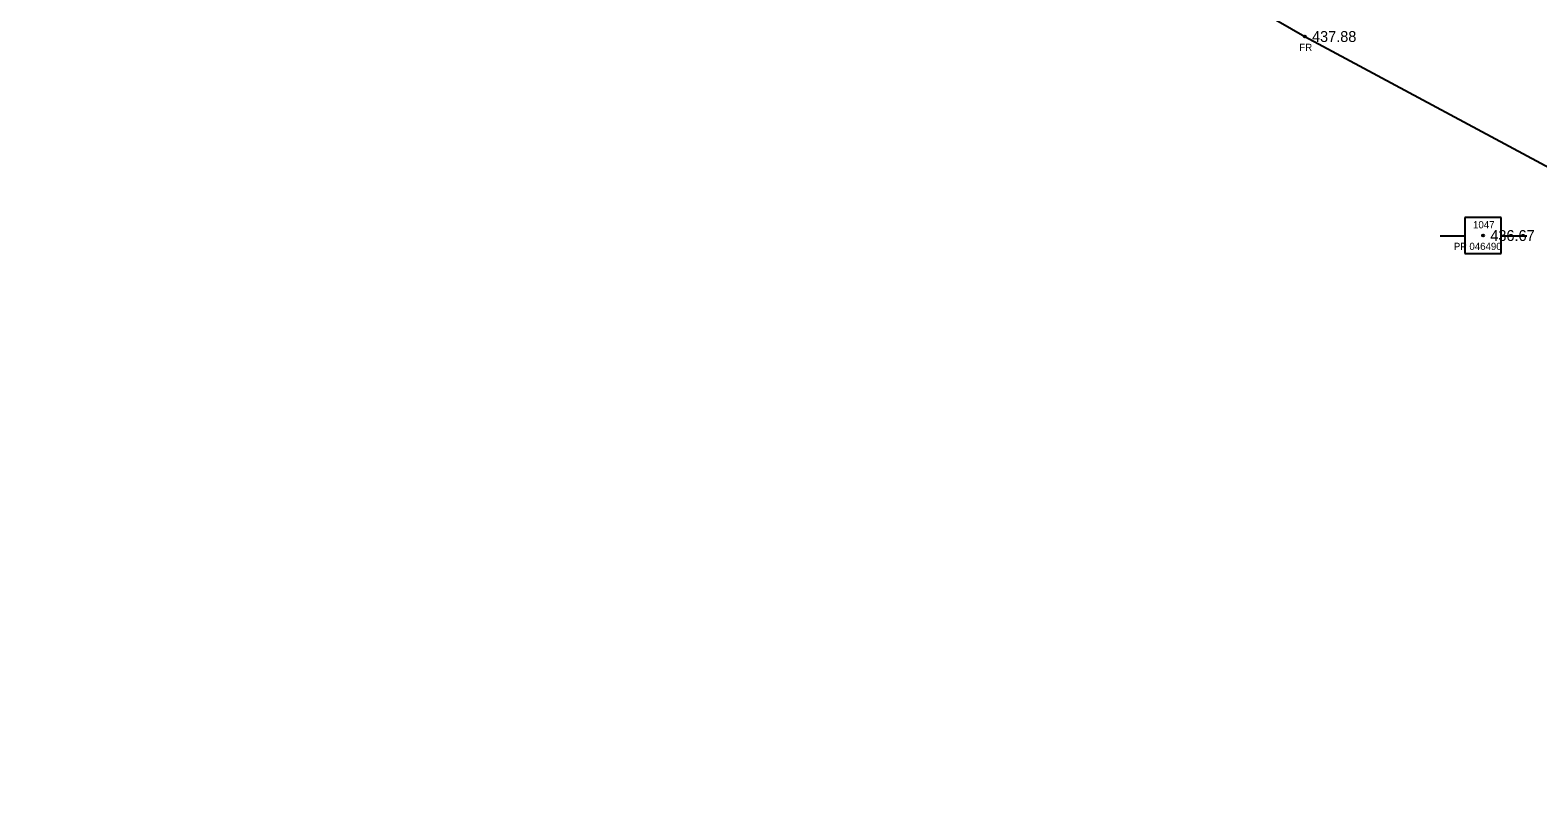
# Model space of a CAD drawing. Extents: x 1611865 to 1617004, y 775289 to 778546.
# Drawn here: x 1613852.1 to 1614060.8, y 777874.5 to 777980.8 of the extents above; entities that cross this region are included whole.
import ezdxf

# ---------------------------------------------------------------- set-up
doc = ezdxf.new("R2010")
doc.units = 0
for name, color, linetype in [('Default', 7, 'Continuous'), ('RD_EX_Fence_Other', 7, 'Continuous'), ('RD_EX_Fence_Other_txCode', 7, 'Continuous'), ('RD_EX_TX_Fence_Other_ELEV', 7, 'Continuous'), ('RD_EX_UT', 7, 'Continuous'), ('RD_EX_UT_txCode', 7, 'Continuous'), ('RD_HC_Cl', 7, 'Continuous'), ('RD_HC_Survey_ELEV', 7, 'Continuous'), ('RD_SMD_Locator', 7, 'Continuous')]:
    doc.layers.add(name, color=color, linetype=linetype)

msp = doc.modelspace()

# ---------------------------------------------------------------- linework, layer by layer
at = {"layer": 'Default'}
msp.add_arc((1613334.62, 776765.46), 1432.38, 51.01411, 67.14296, dxfattribs=at)
msp.add_arc((1613334.62, 776765.46), 1432.38, 51.01411, 67.14296, dxfattribs=at)
at = {"layer": 'RD_EX_Fence_Other'}
msp.add_lwpolyline([(1613852.08, 778066.01), (1613898.03, 778046.63), (1613942.24, 778026.73), (1613986.54, 778004.12), (1614028.52, 777979.95), (1614066.85, 777959.39), (1614112.82, 777929.4), (1614150.64, 777902.78), (1614189.71, 777873.35), (1614229.91, 777841.27), (1614268.42, 777810.69), (1614347.33, 777746.8), (1614401.12, 777703.98), (1614396.2, 777691.06)], dxfattribs=at)
at = {"layer": 'RD_EX_UT'}
for p, q in [((1614055.69, 777954.92), (1614050.69, 777954.92)), ((1614050.69, 777954.92), (1614050.69, 777949.92)), ((1614055.69, 777949.92), (1614055.69, 777954.92)), ((1614047.25, 777952.35), (1614050.72, 777952.35)), ((1614055.61, 777952.35), (1614059.25, 777952.35)), ((1614050.69, 777949.92), (1614055.69, 777949.92))]:
    msp.add_line(p, q, dxfattribs=at)
at = {"layer": 'RD_HC_Cl'}
msp.add_arc((1613334.62, 776765.46), 1432.38, 51.01411, 67.14296, dxfattribs=at)
at = {"layer": 'RD_SMD_Locator'}
for centre in [(1614028.52, 777979.95), (1614053.2, 777952.41)]:
    msp.add_circle(centre, 0.15, dxfattribs=at)

# ---------------------------------------------------------------- texts
at = {"layer": 'RD_EX_Fence_Other_txCode'}
msp.add_text('FR', height=1, dxfattribs=at).set_placement((1614027.76, 777977.95))
at = {"layer": 'RD_EX_TX_Fence_Other_ELEV'}
msp.add_text('437.88', height=1.5, dxfattribs=at).set_placement((1614029.52, 777979.2))
at = {"layer": 'RD_EX_UT_txCode'}
for s, p in [('1047', (1614051.81, 777953.41)), ('PP 046490', (1614049.15, 777950.41))]:
    msp.add_text(s, height=1, dxfattribs=at).set_placement(p)
at = {"layer": 'RD_HC_Survey_ELEV'}
msp.add_text('436.67', height=1.5, dxfattribs=at).set_placement((1614054.2, 777951.66))

doc.saveas('drawing.dxf')
